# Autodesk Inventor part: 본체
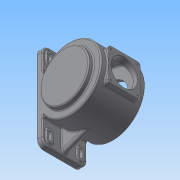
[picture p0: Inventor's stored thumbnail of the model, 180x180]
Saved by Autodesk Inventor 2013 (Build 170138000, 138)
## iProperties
Created: 2015-06
Part Number: 본체
Material: 일반
Document SubType Name: Modeling
Designer: ST4
Density: 1 g/cm^3
Author: ST4
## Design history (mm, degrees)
sketch "스케치1"
  geometry: C1 r 85 at (0, 0); 1 further point
  constraints: 1 centre point, 1 coincident
  dimensions: "d0" = 170 diameter of C1
extrude "돌출1" new body sketch "스케치1" stored distance "d2" = 118; taper "d3" = 0 deg
node "작업 평면2"
sketch "스케치9"
  geometry: L1 (-115, 59)-(115, 59); L2 (115, 59)-(115, -59); L3 (115, -59)-(-115, -59); L4 (-115, -59)-(-115, 59); 3 further points
  constraints: 8 end point, 2 midpoint, 2 parallel, 1 horizontal, 1 horizontal alignment, 1 perpendicular, 1 vertical alignment
  dimensions: "d38" = 230 distance of L1.start L1.end; "d40" = 118 distance of L3.end L1.start
extrude "돌출8" join sketch "스케치9" distance "d41" = 14; taper "d42" = 0 deg
sketch "스케치2"
  geometry: C1 r 85 at (0, 0) reference; C2 r 65 at (0, 0)
  constraints: 1 centre point, 1 coincident
  dimensions: "d4" = 130 diameter of C2
extrude "돌출2" join sketch "스케치2" distance "d6" = 13; taper "d7" = 0 deg
sketch "스케치3"
  geometry: C1 r 85 at (0, 0) reference; C2 r 65 at (0, 0)
  constraints: 1 centre point, 1 coincident
  dimensions: "d8" = 130 diameter of C2
extrude "돌출3" join sketch "스케치3" distance "d10" = 3; taper "d11" = 0 deg
sketch "스케치4"
  geometry: L1 (-85, -59)-(-85, 59) reference; L2 (-65, -62)-(65, -62) reference; L3 (65, 72)-(-65, 72) reference; L4 (0, 72)-(0, -62); L5 (0, 64.5)-(15, 64.5); L6 (15, 64.5)-(15, 61.5); L7 (15, 61.5)-(23.5, 61.5); L8 (23.5, 61.5)-(23.5, 47.5); L9 (23.5, 47.5)-(31, 47.5); L10 (31, 47.5)-(32.632, 51); L11 (32.632, 51)-(77, 51); L12 (77, 51)-(77, -51); L13 (77, -51)-(47.5, -51); L14 (85, 59)-(-85, 59) reference; L15 (47.5, -51)-(47.5, -62); 1 further point
  constraints: 22 end point, 5 parallel, 5 perpendicular, 3 point on line, 2 midpoint
  dimensions: "d12" = 154 diameter of L12 L4; "d14" = 30 diameter of L6 L4; "d15" = 47 diameter of L8 L4; "d16" = 115 deg angle of L10 L11; "d17" = 62 diameter of L9.end L4; "d18" = 3.5 distance between parallel lines of L9 L11; "d19" = 102 distance between parallel lines of L13 L11; "d20" = 3 distance between parallel lines of L7 L5; "d21" = 14 distance of L7.end L8.end; "d22" = 8 distance between parallel lines of L11 L14; "d23" = 95 diameter of L15 L4
revolve "회전1" sketch "스케치4" stored, may be unused: angle "d24" = 90 deg
node "작업 평면1"
sketch "스케치5"
  geometry: L1 (-42.5, 42.5)-(42.5, 42.5); L2 (42.5, 42.5)-(42.5, -42.5); L3 (42.5, -42.5)-(-42.5, -42.5); L4 (-42.5, -42.5)-(-42.5, 42.5); 3 further points
  constraints: 8 end point, 2 midpoint, 2 parallel, 1 horizontal, 1 horizontal alignment, 1 perpendicular, 1 vertical alignment
  dimensions: "d25" = 85 distance of L1.start L1.end; "d27" = 85 distance of L1.end L2.end
extrude "돌출4" join sketch "스케치5" distance "d28" = 3; taper "d29" = 0 deg
sketch "스케치6"
  geometry: L1 (42.5, 0)-(-42.5, 0) reference; L2 (42.5, 0)-(42.5, 42.5) reference; L3 (42.5, 42.5)-(-42.5, 42.5) reference; L4 (-42.5, 42.5)-(-42.5, 0) reference; 1 further point
extrude "돌출5" join sketch "스케치6" stored distance "d30" = 3; taper "d31" = 0 deg
sketch "스케치7"
  geometry: L1 (42.5, 0)-(-42.5, 0) reference; L2 (-42.5, 0)-(-42.5, -42.5) reference; L3 (-42.5, -42.5)-(42.5, -42.5) reference; L4 (42.5, -42.5)-(42.5, 0) reference; 1 further point
extrude "돌출6" join sketch "스케치7" stored distance "d32" = 3; taper "d33" = 0 deg
sketch "스케치8"
  geometry: C1 r 35 at (0, 0); 1 further point
  constraints: 1 centre point, 1 coincident
  dimensions: "d34" = 70 diameter of C1
extrude "돌출7" cut sketch "스케치8" stored distance "d36" = 3; taper "d37" = 0 deg
sketch "스케치10"
  geometry: L1 (32, -81)-(50, -81); L2 (50, -81)-(50, -97); L3 (50, -97)-(32, -97); L4 (32, -97)-(32, -81); A1 r 9 centre (41, -81) between (50, -81) and (32, -81); A2 r 9 centre (41, -97) between (32, -97) and (50, -97); 1 further point
  constraints: 8 end point, 4 point on circle, 2 centre point, 2 parallel, 2 tangent, 1 equal radius, 1 horizontal, 1 perpendicular
  dimensions: "d43" = 18 distance of L1.start L1.end; "d45" = 16 distance of L1.end L2.end; "d46" = 97 distance from line of L3 point (0, 0); "d97" = 41 horizontal distance of point (0, 0) A2.centre
extrude "돌출9" join sketch "스케치10" distance "d48" = 3; taper "d49" = 0 deg
sketch "스케치11"
  geometry: L1 (32, -81)-(32, -97) reference; L2 (50, -97)-(50, -81) reference; L3 (45, -81)-(45, -97); L4 (37, -97)-(37, -81); A1 r 9 centre (41, -81) between (50, -81) and (32, -81) reference; A2 r 9 centre (41, -97) between (32, -97) and (50, -97) reference; A3 r 4 centre (41, -81) between (45, -81) and (37, -81); A4 r 4 centre (41, -97) between (37, -97) and (45, -97); 1 further point
  constraints: 4 end point, 4 point on circle, 2 centre point, 3 other
  dimensions: "d50" = 8 distance between parallel lines of L3 L4
extrude "돌출10" cut sketch "스케치11" stored distance "d52" = 3; taper "d53" = 0 deg
sketch "스케치12"
  geometry: L1 (71, -46.733)-(71, -115) reference; L2 (4.703, -84.87)-(71, -109); A1 r 85 centre (0, 0) between (71, 46.733) and (71, -46.733) reference; 1 further point
  constraints: 2 end point, 1 point on circle, 1 point on line
  dimensions: "d54" = 110 deg angle of L1 L2; "d55" = 6 distance of L1.end L2.end
extrude "돌출11" join sketch "스케치12" stored distance "d56" = 15; taper "d57" = 0 deg
sketch "스케치13"
  geometry: C1 r 47.5 at (0, 0) reference; 1 further point
  constraints: 1 horizontal alignment
  dimensions: "d58" = 55 distance of C1.centre point (-55, 0)
hole "구멍1" sketch "스케치13" at (-55, 0) diameter "d59" = 3.242; stored, may be unused: countersink angle "d63" = 90 deg, drill point angle "d65" = 118 deg; dims "d60" = 6, "d61" = 4, "d62" = 2, "d64" = 12
sketch "스케치14"
  geometry: C1 r 35 at (0, 0) reference; 1 further point
  dimensions: "d69" = 35.5 horizontal distance of C1.centre point (-35.5, 35.5); "d70" = 35.5 horizontal distance of C1.centre point (-35.5, 35.5)
hole "구멍2" sketch "스케치14" at (-35.5, 35.5) diameter "d71" = 3.242; stored, may be unused: countersink angle "d75" = 90 deg, drill point angle "d77" = 118 deg; dims "d72" = 10, "d73" = 4, "d74" = 2, "d76" = 13
sketch "스케치15"
  geometry: L1 (-71, 115)-(-71, 46.733) reference; L2 (-85, 115)-(-71, 115) reference; L3 (-85, 115)-(-85, -115) reference; L4 (-85, -115)-(-71, -115) reference; L5 (-71, -46.733)-(-71, -115) reference; L6 (0, 0)-(35.923, -77.036); L7 (0, 0)-(0, -85); L8 (99.057, -47.596)-(-41.047, -112.928); C1 r 65 at (0, 0) reference; A1 r 85 centre (0, 0) between (-71, -46.733) and (-71, 46.733) reference
  constraints: 6 end point, 2 point on circle, 1 parallel, 1 point on line
  dimensions: "d78" = 25 deg angle of L7 L6; "d79" = 90 deg angle of L8 L6
sketch "스케치16"
  geometry: L1 (71, -115)-(71, -46.733) reference; L2 (85, -115)-(71, -115) reference; L3 (85, -115)-(85, 115) reference; L4 (85, 115)-(71, 115) reference; L5 (71, 46.733)-(71, 115) reference; L6 (-99.057, -47.596)-(41.047, -112.928) reference; C1 r 65 at (0, 0) reference; A1 r 85 centre (0, 0) between (71, 46.733) and (71, -46.733) reference; 1 further point
  constraints: 1 point on circle, 1 point on line
node "작업 평면3"
sketch "스케치17"
  geometry: 2 further points
  constraints: 2 coincident, 1 other
feature "엠보싱1" sketch "스케치17" dims "d80" = 0.5, "d81" = 0
fillet "모깎기1" dims "d82" = 7
fillet "모깎기2" dims "d83" = 18
fillet "모깎기3" dims "d84" = 3
fillet "모깎기4" dims "d85" = 7.5
fillet "모깎기5" dims "d86" = 3
fillet "모깎기6" dims "d87" = 3
fillet "모깎기7" dims "d88" = 3
fillet "모깎기8" dims "d89" = 3
fillet "모깎기9" dims "d90" = 0.3
chamfer "모따기1" distance "d91" = 1; stored, may be unused: second distance "d92" = 2, angle "d93" = 45 deg
fillet "모깎기10" dims "d94" = 0.3
fillet "모깎기11" dims "d95" = 3
fillet "모깎기12" dims "d96" = 2.9
chamfer "모따기2" distance "d98" = 1; stored, may be unused: second distance "d99" = 2, angle "d100" = 45 deg
node "솔리드1"
mirror "대칭1"
mirror "대칭2"
mirror "대칭3"
pattern_circular "원형 패턴1" dims angle "d67" = 360 deg
mirror "대칭4"
mirror "대칭5"
